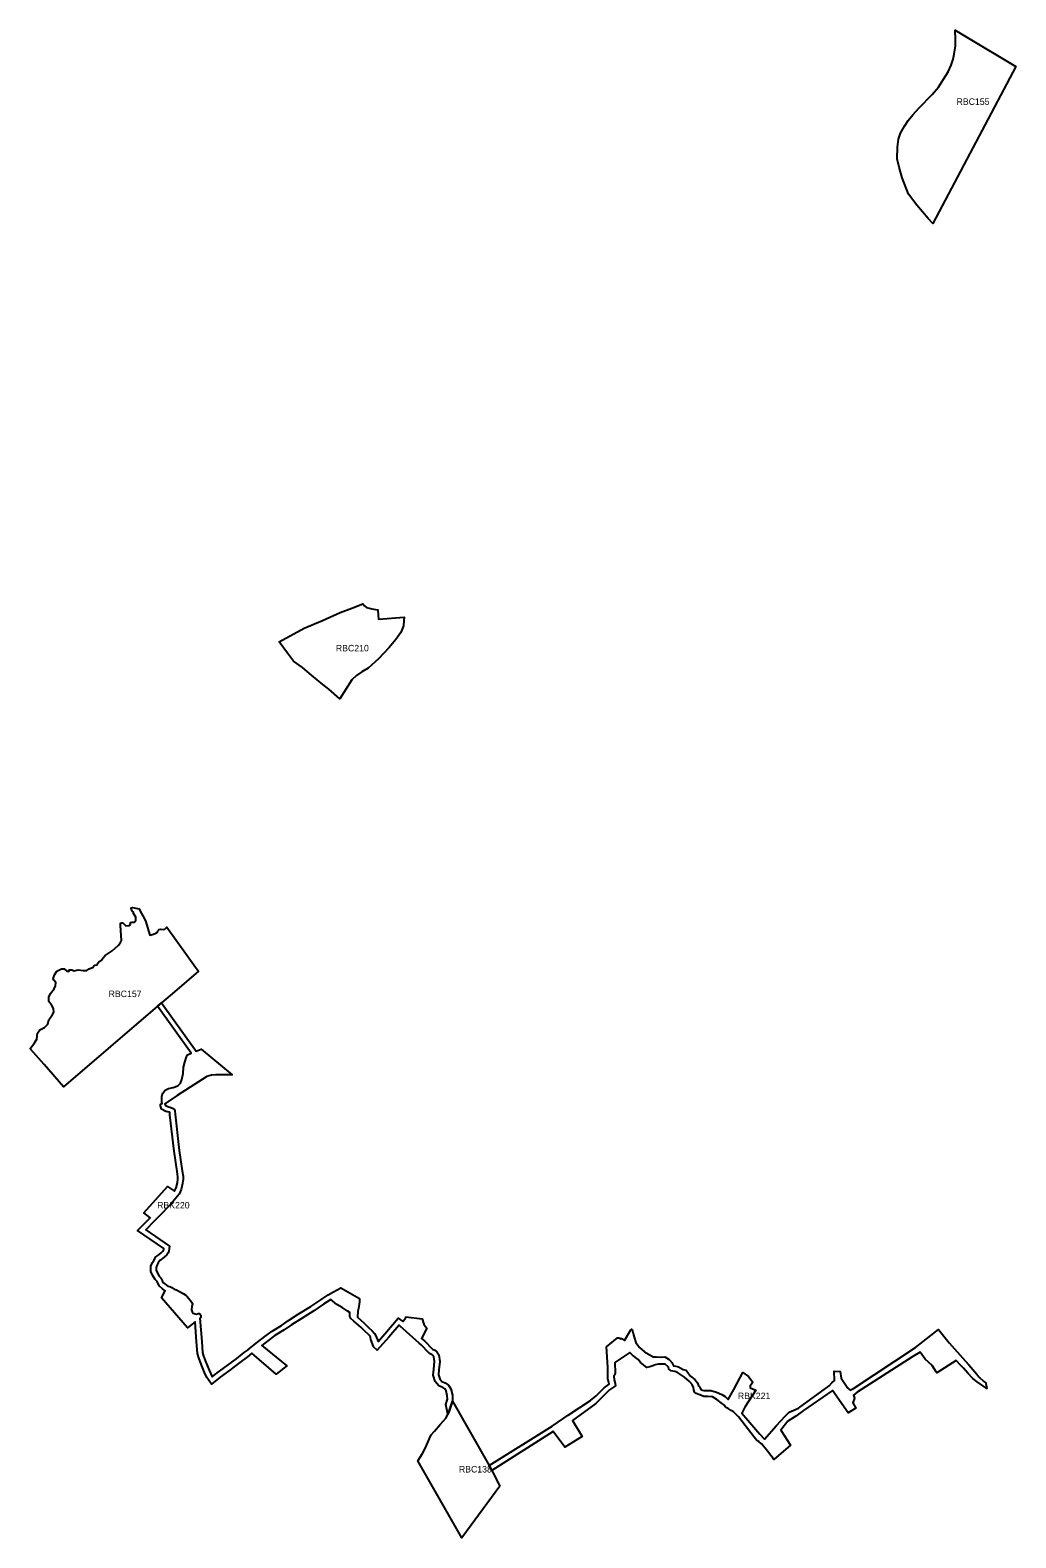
# Model space of a CAD drawing. Extents: x -559776 to -467147, y -1204122 to -1132159.
# Drawn here: x -542167 to -534606, y -1188336 to -1176775 of the extents above; entities that cross this region are included whole.
import ezdxf

# ---------------------------------------------------------------- set-up
doc = ezdxf.new("R2010")
doc.units = 0
doc.layers.add('regionalni_biocentrum_biokoridor', color=7, linetype='Continuous')

msp = doc.modelspace()

# ---------------------------------------------------------------- linework, layer by layer
at = {"layer": 'regionalni_biocentrum_biokoridor'}
for points in [[(-535194.24, -1178166.28), (-535242.9, -1178258.39), (-535278.55, -1178219.63), (-535367.23, -1178117.81), (-535429.41, -1178032.29), (-535477.32, -1177908.07), (-535502.8, -1177824.59), (-535516.05, -1177761.05), (-535515.03, -1177672.48), (-535506.88, -1177610.37), (-535491.59, -1177564.55), (-535461.01, -1177511.61), (-535432.47, -1177468.85), (-535396.79, -1177425.07), (-535348.88, -1177371.11), (-535247.97, -1177267.26), (-535201.08, -1177213.29), (-535160.3, -1177150.17), (-535125.64, -1177094.17), (-535103.22, -1177043.26), (-535086.91, -1176998.47), (-535079.06, -1176958.65), (-535068.87, -1176894.51), (-535068.87, -1176844.62), (-535072.15, -1176774.97), (-535034.8, -1176797.33), (-534982.94, -1176828.38), (-534606.5, -1177053.76)], [(-539497.2, -1181262.05), (-539494.65, -1181292.04), (-539298.79, -1181275.48), (-539300.29, -1181304.08), (-539303.31, -1181341.7), (-539322.89, -1181392.86), (-539363.57, -1181448.54), (-539413.29, -1181508.74), (-539494.65, -1181596.02), (-539575.4, -1181668.39), (-539622.11, -1181695.47), (-539664.29, -1181724.05), (-539698.94, -1181757.15), (-539792.35, -1181903.07), (-539875.22, -1181829.36), (-539921.92, -1181791.75), (-540008.93, -1181721.8), (-540078.23, -1181662.37), (-540147.54, -1181612.73), (-540193.8, -1181551.24), (-540258.42, -1181465.36), (-540065.01, -1181361.66), (-539924.77, -1181302.92), (-539790.57, -1181241.16), (-539700.09, -1181206.52), (-539615.09, -1181174.75), (-539601.62, -1181188.2), (-539588.06, -1181201.75), (-539545.87, -1181212.28), (-539500.67, -1181221.31)], [(-540975.46, -1183853.24), (-540899.9, -1183959.08), (-540876.62, -1183991.69), (-541060.32, -1184148.95), (-541159.4, -1184233.78), (-541189.9, -1184259.89), (-541911.84, -1184877.97), (-542059.53, -1184707.76), (-542161.37, -1184590.39), (-542167.39, -1184583.45), (-542155.08, -1184567.95), (-542133.48, -1184540.74), (-542116.89, -1184512.13), (-542110.86, -1184465.46), (-542094.28, -1184439.87), (-542058.09, -1184423.31), (-542030.95, -1184397.71), (-542024.92, -1184363.08), (-541994.77, -1184322.44), (-541985.72, -1184305.88), (-541987.23, -1184277.27), (-542002.31, -1184253.18), (-542024.92, -1184224.58), (-542023.41, -1184191.46), (-542011.35, -1184161.35), (-541984.21, -1184126.72), (-541972.15, -1184102.63), (-541969.14, -1184078.54), (-541985.72, -1184060.48), (-541990.24, -1184049.94), (-541981.2, -1184018.32), (-541963.11, -1183989.72), (-541926.92, -1183973.16), (-541907.32, -1183973.16), (-541884.7, -1183991.22), (-541874.15, -1183992.73), (-541866.61, -1183980.69), (-541848.52, -1183980.69), (-541830.42, -1183988.21), (-541798.76, -1183980.69), (-541761.07, -1183985.2), (-541732.42, -1183986.71), (-541714.78, -1183973.23), (-541696.69, -1183964.2), (-541683.12, -1183962.69), (-541680.1, -1183952.15), (-541669.55, -1183946.13), (-541652.96, -1183941.61), (-541645.42, -1183928.06), (-541637.88, -1183916.01), (-541619.79, -1183905.47), (-541609.24, -1183890.41), (-541591.14, -1183870.83), (-541538.37, -1183834.68), (-541491.63, -1183794.02), (-541473.54, -1183769.93), (-541467.51, -1183754.87), (-541470.53, -1183678.06), (-541473.54, -1183640.41), (-541473.54, -1183622.34), (-541464.49, -1183620.84), (-541456.96, -1183620.84), (-541447.91, -1183626.86), (-541432.83, -1183643.43), (-541404.19, -1183640.41), (-541398.15, -1183628.37), (-541396.65, -1183617.82), (-541387.6, -1183614.81), (-541366.49, -1183616.32), (-541357.45, -1183599.75), (-541355.94, -1183575.66), (-541375.54, -1183548.55), (-541375.54, -1183539.51), (-541386.09, -1183531.98), (-541390.62, -1183522.95), (-541392.12, -1183506.38), (-541383.08, -1183501.86), (-541331.81, -1183513.91), (-541322.77, -1183530.48), (-541303.17, -1183566.62), (-541282.06, -1183604.27), (-541248.89, -1183715.71), (-541220.24, -1183708.18), (-541203.66, -1183700.65), (-541190.09, -1183693.12), (-541188.58, -1183682.58), (-541181.04, -1183672.04), (-541165.96, -1183669.03), (-541147.87, -1183672.04), (-541134.3, -1183669.03), (-541117.71, -1183653.97)], [(-538926.65, -1187289.4), (-538952.51, -1187365.21), (-538963.57, -1187387.31), (-538977.95, -1187313.51), (-538967.2, -1187273.29), (-538968.02, -1187247.4), (-538976.81, -1187210.22), (-538987.74, -1187193.41), (-539002.71, -1187182.76), (-539032.71, -1187170.42), (-539061.77, -1187137.62), (-539076.53, -1187089.97), (-539071.91, -1187044.13), (-539064.98, -1186985.35), (-539071.1, -1186948.18), (-539077.73, -1186937.37), (-539084.59, -1186931.83), (-539105.39, -1186921.86), (-539129.8, -1186897.49), (-539151.18, -1186873.85), (-539168.55, -1186855.83), (-539182.84, -1186844.42), (-539328.62, -1186713.85), (-539337.9, -1186705.53), (-539415.43, -1186797.38), (-539504.81, -1186897.97), (-539534.71, -1186871.41), (-539533.15, -1186869.65), (-539553.84, -1186816.08), (-539555.89, -1186799.66), (-539560.03, -1186790.71), (-539572.25, -1186776.39), (-539599.57, -1186751.26), (-539631.62, -1186720), (-539683.39, -1186674.98), (-539707.7, -1186654.97), (-539714.87, -1186638.39), (-539716, -1186621.82), (-539714.76, -1186608.79), (-539735.43, -1186596.01), (-539773.16, -1186570.39), (-539815.42, -1186546.28), (-539859.91, -1186507.69), (-539916.67, -1186543.49), (-539992.16, -1186594.74), (-540089.71, -1186655.91), (-540162.48, -1186703.86), (-540218.63, -1186741), (-540289.57, -1186785.75), (-540343.05, -1186824.54), (-540390.49, -1186861.4), (-540199.7, -1187017.09), (-540280.73, -1187080.04), (-540466.46, -1186921.32), (-540499.8, -1186947.29), (-540557.74, -1186992.98), (-540635.45, -1187050.81), (-540708.68, -1187103.06), (-540775.63, -1187157.4), (-540812.12, -1187106.63), (-540830.98, -1187067.46), (-540856.63, -1187003.57), (-540874.73, -1186956.1), (-540883.78, -1186922.95), (-540890.57, -1186833.52), (-540902.48, -1186681.1), (-540960.71, -1186725.83), (-541159.82, -1186496.82), (-541130.67, -1186442.46), (-541151.37, -1186426.95), (-541174.84, -1186407.59), (-541191.67, -1186379.13), (-541193.19, -1186371.54), (-541195.13, -1186369.31), (-541208.98, -1186355.48), (-541229.58, -1186320.87), (-541241.3, -1186292.77), (-541241.3, -1186254.13), (-541228.25, -1186225.88), (-541219.73, -1186209.11), (-541202.66, -1186180.7), (-541186.76, -1186170.93), (-541176.61, -1186162.69), (-541162.46, -1186151.38), (-541149.29, -1186139.32), (-541144.16, -1186131.21), (-541141.93, -1186126.75), (-541140.75, -1186118.49), (-541343.21, -1185980.22), (-541246.84, -1185881.76), (-541248.06, -1185880.71), (-541295.57, -1185843.81), (-541113.81, -1185641.99), (-541058.88, -1185678.55), (-541046.39, -1185652.03), (-541037.89, -1185612.88), (-541034.03, -1185583.91), (-541034.59, -1185567.52), (-541040.32, -1185526.8), (-541063.01, -1185372.11), (-541094.89, -1185092.07), (-541095.76, -1185075.95), (-541102.22, -1185073.11), (-541125.79, -1185066.83), (-541160.93, -1185049.28), (-541168.67, -1185024.03), (-541166.4, -1185011.98), (-541155.27, -1185004.57), (-541156.05, -1184999.1), (-541156.05, -1184975), (-541156.05, -1184950.9), (-541149.27, -1184926.05), (-541131.92, -1184904.2), (-541107.04, -1184890.16), (-541071.6, -1184884.14), (-541035.41, -1184869.83), (-541014.29, -1184848.75), (-541002.98, -1184820.89), (-540992.43, -1184776.47), (-540990.92, -1184726.78), (-540981.12, -1184689.13), (-540969.05, -1184647.72), (-540960.76, -1184631.91), (-540931.42, -1184619.81), (-541189.9, -1184259.89), (-541159.4, -1184233.78), (-540893.42, -1184604.14), (-540854.96, -1184588.28), (-540617.7, -1184784.79), (-540743.61, -1184787.05), (-540776.79, -1184788.55), (-540812, -1184799.93), (-541039.69, -1184945.23), (-541134.39, -1185008.73), (-541129.66, -1185020.19), (-541111.56, -1185029.23), (-541088.94, -1185035.25), (-541070.09, -1185043.54), (-541063.31, -1185049.56), (-541056.52, -1185060.86), (-541055.01, -1185088.73), (-541023.34, -1185366.94), (-541000.72, -1185521.11), (-540994.69, -1185564.04), (-540993.94, -1185585.88), (-540998.46, -1185619.77), (-541008.26, -1185664.96), (-541025.22, -1185700.96), (-541023.31, -1185702.23), (-541088.93, -1185777.54), (-541177.92, -1185869.42), (-541216.38, -1185907.82), (-541281.24, -1185974.09), (-541097.62, -1186099.5), (-541103.25, -1186138.85), (-541109.29, -1186150.9), (-541118.34, -1186165.22), (-541136.44, -1186181.79), (-541151.52, -1186193.84), (-541163.59, -1186203.64), (-541173.4, -1186209.66), (-541184.71, -1186228.49), (-541192.25, -1186243.33), (-541201.3, -1186262.92), (-541201.3, -1186284.77), (-541193.76, -1186302.85), (-541177.17, -1186330.72), (-541165.85, -1186342.02), (-541156.05, -1186353.32), (-541153.79, -1186364.62), (-541143.98, -1186381.19), (-541111.98, -1186407.6), (-541096.46, -1186409), (-541080.61, -1186416.54), (-541062.51, -1186429.72), (-541045.91, -1186434.62), (-541025.91, -1186443.66), (-540993.47, -1186464), (-540973.1, -1186475.3), (-540964.04, -1186485.47), (-540953.48, -1186498.66), (-540936.5, -1186515.61), (-540925.94, -1186532.18), (-540922.17, -1186543.86), (-540927.45, -1186560.06), (-540929.71, -1186587.56), (-540924.05, -1186602.63), (-540916.51, -1186612.71), (-540901.79, -1186618.36), (-540891.23, -1186620.62), (-540879.28, -1186616.4), (-540867.94, -1186617.36), (-540858.89, -1186627.91), (-540858.34, -1186647.18), (-540864.63, -1186652.02), (-540850.69, -1186830.45), (-540844.18, -1186916.11), (-540836.66, -1186943.68), (-540819.38, -1186988.99), (-540794.36, -1187051.31), (-540770.21, -1187101.48), (-540732.93, -1187071.22), (-540659.01, -1187018.48), (-540582.07, -1186961.23), (-540524.75, -1186916.02), (-540496.32, -1186895.8), (-540498.06, -1186894.31), (-540422.29, -1186835.45), (-540367.07, -1186792.55), (-540312, -1186752.61), (-540240.34, -1186707.4), (-540184.51, -1186670.48), (-540111.34, -1186622.26), (-540014.02, -1186561.24), (-539938.58, -1186510.02), (-539881.24, -1186473.86), (-539841.08, -1186449.83), (-539783.73, -1186419.69), (-539640.35, -1186501.07), (-539640.35, -1186526.69), (-539648.84, -1186576.61), (-539653.37, -1186598.08), (-539657.14, -1186644.8), (-539604.51, -1186690.57), (-539572.06, -1186722.22), (-539543.39, -1186748.59), (-539526.03, -1186768.93), (-539516.98, -1186788.52), (-539498.36, -1186830.5), (-539445.67, -1186771.19), (-539344.55, -1186651.39), (-539309.08, -1186677.01), (-539287.95, -1186650.63), (-539286.45, -1186640.84), (-539161.18, -1186658.17), (-539146.84, -1186698.1), (-539136.28, -1186713.17), (-539123.45, -1186728.24), (-539164.26, -1186808.07), (-539141.56, -1186826.2), (-539121.94, -1186846.54), (-539100.81, -1186869.9), (-539081.95, -1186888.74), (-539063.08, -1186897.78), (-539047.24, -1186910.59), (-539032.9, -1186933.95), (-539024.6, -1186984.43), (-539032.14, -1187048.47), (-539035.92, -1187085.89), (-539026.11, -1187117.55), (-539008.92, -1187136.96), (-538983.26, -1187147.51), (-538958.35, -1187165.23), (-538939.49, -1187194.25), (-538928.17, -1187242.11)], [(-537534.22, -1186798.68), (-537520.24, -1186838.23), (-537492.29, -1186877.78), (-537456.19, -1186910.35), (-537389.35, -1186948.34), (-537363.33, -1186948.95), (-537326.43, -1186950.26), (-537298.75, -1186947.63), (-537265.8, -1186970.01), (-537244.71, -1186991.07), (-537231.53, -1187017.4), (-537214.4, -1187018.72), (-537193.31, -1187025.3), (-537159.05, -1187045.05), (-537136.64, -1187051.63), (-537118.19, -1187075.32), (-537100.88, -1187096.4), (-537069.25, -1187122.76), (-537049.22, -1187148.06), (-537040.43, -1187171.43), (-537033.84, -1187179.32), (-537020.75, -1187201.83), (-536999.67, -1187206.05), (-536946.95, -1187206.05), (-536901.62, -1187218.7), (-536862.61, -1187237.68), (-536836.26, -1187252.44), (-536814.12, -1187276.69), (-536768.78, -1187199.72), (-536700.26, -1187067.94), (-536657.03, -1187099.57), (-536624.35, -1187141.74), (-536634.89, -1187157.55), (-536643.32, -1187170.2), (-536644.38, -1187184.96), (-536601.15, -1187204.99), (-536685.5, -1187334.67), (-536707.64, -1187380), (-536569.53, -1187541.31), (-536535.79, -1187579.26), (-536443.01, -1187474.89), (-536375.15, -1187403.64), (-536344.97, -1187373.68), (-536273.28, -1187341), (-536039.23, -1187171.26), (-536017.09, -1187147.01), (-535998.11, -1187129.09), (-536001.27, -1187059.51), (-535954.02, -1187062.13), (-535945.56, -1187112.81), (-535895.43, -1187187.9), (-535877.92, -1187202.89), (-535851.57, -1187192.34), (-535377.14, -1186877.12), (-535201.08, -1186740.06), (-535117.79, -1186841.27), (-534993.44, -1186981.4), (-534967.03, -1187008.9), (-534936.46, -1187044.75), (-534904.83, -1187080.59), (-534889.47, -1187100.54), (-534851.81, -1187136.43), (-534836.23, -1187148.96), (-534836.12, -1187152.12), (-534834.81, -1187166.5), (-534832.94, -1187179.62), (-534830.3, -1187190.74), (-534843.78, -1187180.53), (-534902.22, -1187140.97), (-534936.06, -1187115.63), (-534975.53, -1187073.39), (-535007.77, -1187035.78), (-535027.58, -1187015.54), (-535064.26, -1186976.34), (-535211.8, -1187070.76), (-535218.12, -1187063.6), (-535249.06, -1187014.26), (-535301.24, -1186965.68), (-535341.3, -1186912.96), (-535396.12, -1186945.64), (-535824.16, -1187219.75), (-535852.62, -1187241.89), (-535844.05, -1187264.86), (-535858.15, -1187301.46), (-535832.77, -1187340.88), (-535891.99, -1187377.49), (-536012.87, -1187207.1), (-536234.27, -1187361.03), (-536295.42, -1187404.25), (-536354.6, -1187441.92), (-536401.04, -1187499.66), (-536409.58, -1187509.57), (-536334.39, -1187625.8), (-536462.49, -1187735.14), (-536465.99, -1187732.82), (-536468.31, -1187728.16), (-536530.03, -1187649.07), (-536556.82, -1187615.34), (-536556.65, -1187615.14), (-536576.91, -1187598.24), (-536592.72, -1187588.75), (-536613.81, -1187563.45), (-536735.05, -1187407.41), (-536771.91, -1187369.21), (-536790.54, -1187361.07), (-536812.67, -1187343.62), (-536823.15, -1187340.13), (-536837.12, -1187328.5), (-536838.87, -1187322.69), (-536866.83, -1187300.93), (-536900.57, -1187275.63), (-536933.31, -1187255.34), (-536970.15, -1187252.44), (-537000.72, -1187253.49), (-537031.3, -1187239.79), (-537057.65, -1187230.3), (-537072.41, -1187218.7), (-537075.58, -1187200.78), (-537079.97, -1187184.59), (-537089.19, -1187160.89), (-537110.37, -1187138.58), (-537147.27, -1187103.78), (-537170.46, -1187087.97), (-537201.22, -1187068.74), (-537222.31, -1187060.84), (-537252.62, -1187055.58), (-537261.85, -1187049), (-537268.44, -1187042.41), (-537269.76, -1187027.93), (-537296.11, -1187004.24), (-537350.15, -1187005.55), (-537384.11, -1187013.34), (-537383.99, -1187015.03), (-537414.27, -1187025.5), (-537437.56, -1187031.32), (-537485.31, -1186991.77), (-537502.78, -1186969.67), (-537547.03, -1186935.94), (-537566.83, -1186915), (-537682.56, -1186991.8), (-537683.28, -1187012.24), (-537683.28, -1187022.71), (-537679.79, -1187042.49), (-537680.95, -1187058.77), (-537680.95, -1187072.73), (-537683.28, -1187086.69), (-537689.1, -1187097.15), (-537686.77, -1187123.91), (-537679.79, -1187154.15), (-537677.46, -1187170.43), (-537722.87, -1187200.68), (-537829.21, -1187305.27), (-538008.36, -1187436.27), (-537933.83, -1187559.02), (-538066.81, -1187642.32), (-538155.96, -1187521.03), (-538624.79, -1187820.13), (-538646.96, -1187781.16), (-538164.49, -1187479.48), (-538039.29, -1187396.51), (-537869.74, -1187284.15), (-537826.91, -1187246.9), (-537765.26, -1187186.26), (-537727.09, -1187157.78), (-537735.68, -1187113.9), (-537736.31, -1187027.47), (-537736.85, -1187027.83), (-537747.33, -1186870.8), (-537661.15, -1186802.17), (-537651.84, -1186802.17), (-537644.85, -1186804.5), (-537642.52, -1186809.15), (-537632.04, -1186806.83), (-537626.22, -1186811.48), (-537608.75, -1186824.27), (-537558.67, -1186740.53), (-537554.02, -1186737.04), (-537550.52, -1186739.36), (-537542.37, -1186768.44)], [(-538563.67, -1187938.98), (-538855.94, -1188336.46), (-539193.52, -1187746.08), (-539156.98, -1187689.09), (-539136.52, -1187651.09), (-539118.99, -1187611.63), (-539104.37, -1187575.1), (-539091.22, -1187547.33), (-539066.38, -1187518.11), (-539021.95, -1187466.2), (-538977.42, -1187414.95), (-538963.57, -1187387.31), (-538952.51, -1187365.21), (-538926.65, -1187289.4), (-538646.96, -1187781.16), (-538639.5, -1187794.27), (-538624.79, -1187820.13), (-538619.68, -1187829.12)]]:
    msp.add_lwpolyline(points, close=True, dxfattribs=at)

# ---------------------------------------------------------------- texts
for s, p in [('RBC155', (-535061.28, -1177348.04)), ('RBC210', (-539822.25, -1181538.91)), ('RBC157', (-541565.48, -1184189.91)), ('RBK220', (-541193.25, -1185810.54)), ('RBK221', (-536738.63, -1187272.72)), ('RBC138', (-538878.6, -1187835.37))]:
    msp.add_text(s, height=50, dxfattribs=at).set_placement(p)

doc.saveas('drawing.dxf')
